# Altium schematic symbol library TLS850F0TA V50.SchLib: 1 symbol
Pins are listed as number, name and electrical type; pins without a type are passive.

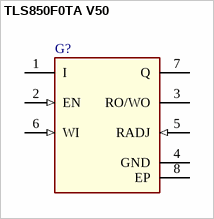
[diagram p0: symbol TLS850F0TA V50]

## TLS850F0TA V50
designator G?  (value not drawn)
Low Dropout Linear Voltage Regulator, Fixed Output Voltage 5V; Manufacturer: Infineon Technologies
footprint TO127P1500X440-8N-1-V
footprint TO127P1500X440-8N-1
pins: 1 I (power) "Input", 2 EN (in) "Enable", 3 RO/WO (oc) "Reset Output / Watchdog Output", 4 GND (power) "Ground", 5 RADJ (in) "Reset Threshold Adjustment", 6 WI (in) "Watchdog Input", 7 Q (power) "Output Voltage", 8 EP (power) "Heat Slug"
